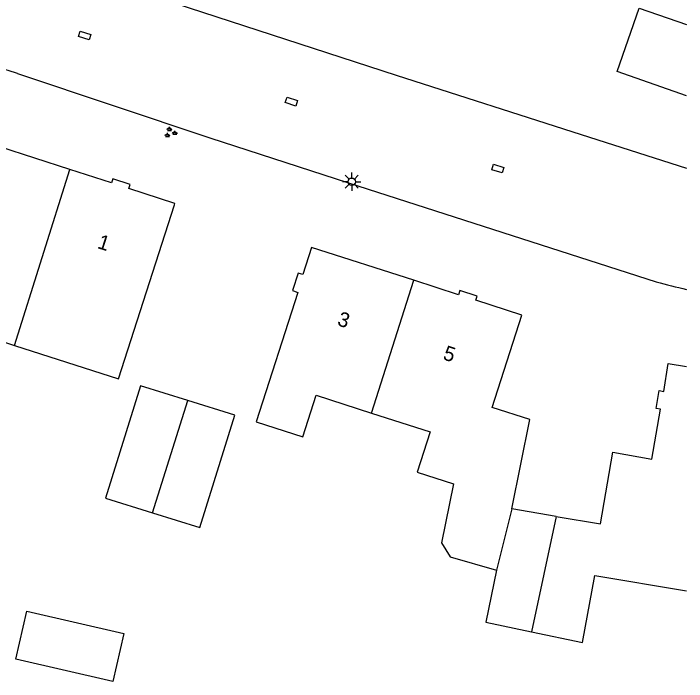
# Model space of a CAD drawing. Extents: x 128999 to 131010, y 395498 to 399007.
# Drawn here: x 130954.29 to 131000, y 396775.63 to 396820.97 of the extents above; entities that cross this region are included whole.
import ezdxf

# ---------------------------------------------------------------- set-up
doc = ezdxf.new("R2010")
doc.units = 0
for name, color, linetype in [('gg-anno-huisnummerreeks BGT', 7, 'Continuous'), ('gg-bbg-bijgebouw', 7, 'Continuous'), ('gg-bbg-gedigitaliseerde bebouwing', 7, 'Continuous'), ('gg-bbg-gedigitaliseerde bijgebouw', 7, 'Continuous'), ('gg-bbg-hoofdgebouw', 7, 'Continuous'), ('gg-bbg-tussenscheiding', 7, 'Continuous'), ('gg-knt-verharding', 7, 'Continuous'), ('gt-symb-groenvak', 7, 'Continuous'), ('gt-symb-kolk center center', 7, 'Continuous'), ('gt-symb-lichtmast', 7, 'Continuous')]:
    doc.layers.add(name, color=color, linetype=linetype)

# ---------------------------------------------------------------- blocks, each defined once
blk = doc.blocks.new('gt0-LMAST')
at = {"layer": 'gt-symb-lichtmast'}
for p, q in [((-0.005, 0.246), (-0.005, 0.621)), ((-0.182, 0.173), (-0.447, 0.438)), ((0.172, 0.173), (0.437, 0.438)), ((-0.255, -0.004), (-0.63, -0.004)), ((-0.182, -0.181), (-0.447, -0.446)), ((-0.005, -0.254), (-0.005, -0.629)), ((0.437, -0.446), (0.172, -0.181)), ((0.245, -0.004), (0.62, -0.004))]:
    blk.add_line(p, q, dxfattribs=at)
blk.add_circle((-0.005, -0.004), 0.25, dxfattribs=at)
blk = doc.blocks.new('gt0-KOLKCC')
at = {"layer": 'gt-symb-kolk center center'}
blk.add_lwpolyline([(-0.375, 0.2), (0.375, 0.2), (0.375, -0.2), (-0.375, -0.2)], close=True, dxfattribs=at)
blk = doc.blocks.new('gt0-GRVAK')
at = {"layer": 'gt-symb-groenvak'}
for p, q in [((-0.11, 0.189), (-0.228, 0.24)), ((-0.182, 0.153), (0.088, 0.153)), ((-0.091, 0.211), (-0.156, 0.322)), ((-0.047, 0.214), (-0.047, 0.393)), ((-0.004, 0.211), (0.061, 0.322)), ((0.015, 0.189), (0.133, 0.24)), ((0.262, -0.052), (0.197, 0.059)), ((0.305, -0.049), (0.305, 0.13)), ((0.349, -0.052), (0.414, 0.059)), ((-0.245, -0.228), (-0.363, -0.177)), ((-0.318, -0.264), (-0.047, -0.264)), ((-0.226, -0.206), (-0.291, -0.095)), ((-0.183, -0.203), (-0.183, -0.024)), ((-0.139, -0.206), (-0.074, -0.095)), ((-0.12, -0.228), (-0.002, -0.177)), ((0.243, -0.074), (0.125, -0.023)), ((0.17, -0.11), (0.441, -0.11)), ((0.368, -0.074), (0.486, -0.023))]:
    blk.add_line(p, q, dxfattribs=at)

msp = doc.modelspace()

# ---------------------------------------------------------------- linework, layer by layer
at = {"layer": 'gg-bbg-bijgebouw'}
msp.add_line((130991.144, 396786.839), (130988.141, 396787.352), dxfattribs=at)
at = {"layer": 'gg-bbg-gedigitaliseerde bebouwing'}
msp.add_line((130947.173, 396800.76), (130954.36, 396798.445), dxfattribs=at)
for points in [[(130954.36, 396798.445), (130961.42, 396796.17), (130965.223, 396807.975)], [(130973.303, 396802.151), (130973.601, 396802.042), (130970.776, 396793.248), (130973.943, 396792.231), (130974.853, 396795.063), (130978.618, 396793.853)], [(130978.618, 396793.853), (130982.583, 396792.579), (130981.702, 396789.837), (130984.177, 396789.042)], [(130984.177, 396789.042), (130983.364, 396785.038), (130983.95, 396784.091), (130987.104, 396783.198)], [(130989.47, 396779.002), (130992.936, 396778.276), (130993.775, 396782.821), (131000, 396781.793)]]:
    msp.add_lwpolyline(points, dxfattribs=at)
at = {"layer": 'gg-bbg-gedigitaliseerde bijgebouw'}
for points in [[(130966.144, 396794.702), (130962.923, 396795.702), (130960.551, 396788.065), (130963.744, 396787.073)], [(130963.744, 396787.073), (130966.959, 396786.075), (130969.331, 396793.712), (130966.144, 396794.702)], [(130987.104, 396783.198), (130986.361, 396779.653), (130989.47, 396779.002)], [(130961.794, 396778.899), (130961.047, 396775.632), (130954.448, 396777.141), (130955.195, 396780.408), (130961.794, 396778.899)]]:
    msp.add_lwpolyline(points, dxfattribs=at)
at = {"layer": 'gg-bbg-hoofdgebouw'}
for points in [[(131000, 396815.372), (130995.283, 396817.019), (130996.785, 396821.322), (131000, 396820.209)], [(130958.124, 396810.373), (130950.966, 396812.685), (130950.378, 396810.836), (130950.084, 396810.931), (130949.704, 396809.751), (130950.002, 396809.655), (130947.173, 396800.76)], [(130965.223, 396807.975), (130965.254, 396808.071), (130962.123, 396809.082), (130962.215, 396809.368), (130961.035, 396809.748), (130960.943, 396809.463), (130958.124, 396810.373)], [(130981.481, 396802.857), (130974.535, 396805.095), (130973.944, 396803.247), (130973.63, 396803.348), (130973.25, 396802.168), (130973.303, 396802.151)], [(130988.141, 396787.352), (130989.348, 396793.406), (130986.81, 396794.237), (130988.824, 396800.491), (130985.693, 396801.5), (130985.785, 396801.786), (130984.605, 396802.166), (130984.513, 396801.88), (130981.481, 396802.857)], [(130991.144, 396786.839), (130994.154, 396786.325), (130994.984, 396791.185), (130997.645, 396790.727), (130998.227, 396794.107), (130997.931, 396794.158), (130998.14, 396795.38), (130998.45, 396795.32), (130998.76, 396797.21), (131000, 396797.005)]]:
    msp.add_lwpolyline(points, dxfattribs=at)
at = {"layer": 'gg-bbg-tussenscheiding'}
for p, q in [((130954.36, 396798.445), (130958.124, 396810.373)), ((130978.618, 396793.853), (130981.481, 396802.857)), ((130963.744, 396787.073), (130966.144, 396794.702)), ((130988.141, 396787.352), (130987.104, 396783.198)), ((130991.144, 396786.839), (130989.47, 396779.002))]:
    msp.add_line(p, q, dxfattribs=at)
at = {"layer": 'gg-knt-verharding'}
for points in [[(130955.893, 396824.722), (130965.245, 396821.665), (130980.274, 396816.784), (130992.836, 396812.744), (131000, 396810.471)], [(130954.579, 396816.89), (130967.624, 396812.535), (130977.04, 396809.469), (130997.947, 396802.757)]]:
    msp.add_lwpolyline(points, dxfattribs=at)
for centre, radius, start, end in [((130952.116, 396810.502), 6.846, 68.9116, 156.9479), ((131014.489, 396863.873), 63.315, 254.85465, 256.771)]:
    msp.add_arc(centre, radius, start, end, dxfattribs=at)

# ---------------------------------------------------------------- block references
at = {"layer": 'gt-symb-groenvak'}
msp.add_blockref('gt0-GRVAK', (130964.942, 396812.881), dxfattribs=at)
at = {"layer": 'gt-symb-kolk center center'}
for p, rotation in [((130959.129, 396819.47), -17.69230089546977), ((130973.17, 396814.989), -17.945563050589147), ((130987.187, 396810.441), -16.98473252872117)]:
    msp.add_blockref('gt0-KOLKCC', p, dxfattribs=dict(at, rotation=rotation))
at = {"layer": 'gt-symb-lichtmast'}
msp.add_blockref('gt0-LMAST', (130977.272, 396809.553), dxfattribs=at)

# ---------------------------------------------------------------- texts
at = {"layer": 'gg-anno-huisnummerreeks BGT'}
for s, p in [('1', (130959.936, 396805.058)), ('3', (130976.223, 396799.823)), ('5', (130983.403, 396797.51))]:
    msp.add_text(s, height=1, rotation=342.1, dxfattribs=at).set_placement(p)

doc.saveas('drawing.dxf')
